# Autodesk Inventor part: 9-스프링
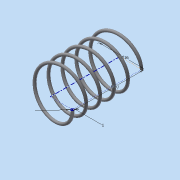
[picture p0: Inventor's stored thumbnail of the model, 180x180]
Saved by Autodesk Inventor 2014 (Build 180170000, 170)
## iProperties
Created: 2015-06
Part Number: 9-스프링
Material: 강철, 연강
Document SubType Name: Modeling
Designer: MYHOME
Density: 7.86 g/cm^3
Appearance: 강철
Mass: 1.52988 g
Surface Area: 7.87024 cm^2
Volume: 0.194641 cm^3
Author: MYHOME
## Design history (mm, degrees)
sketch "스케치1"
  geometry: L1 (0, 0)-(8, 0); L2 (8, 0)-(8, 14.5); L3 (8, 14.5)-(0, 14.5); L4 (0, 14.5)-(0, 0); C1 r 0.5 at (8, 0)
  constraints: 8 end point, 2 parallel, 1 centre point, 1 coincident, 1 horizontal, 1 perpendicular
  dimensions: "d0" = 1 diameter of C1; "d1" = 16 diameter of L2 L4; "d2" = 14.5 distance of L1.end L2.end (derived)
feature "코일1" sketch "스케치1" pitch "d3" = 10; turns "d5" = 5; dims "d4" = 14.5 (= d2), "d6" = 0, angle "d7" = 90 deg, angle "d8" = 90 deg, "d9" = 0, "d10" = 0
sketch "스케치2"
  geometry: L1 (-8.5, 0)-(-7.5, 0) reference; 1 further point
  constraints: 1 horizontal alignment
extrude "돌출1" cut sketch "스케치2" stored distance "d11" = 10; taper "d12" = 0 deg
node "작업 평면1"
sketch "스케치3"
  geometry: L1 (-7.5, 0)-(-8.5, 0) reference; 1 further point
  constraints: 1 horizontal alignment
extrude "돌출2" cut sketch "스케치3" stored distance "d14" = 10; taper "d15" = 0 deg
node "솔리드1"
node "절단 모서리 투영1"
node "절단 모서리 투영2"
other parameters: "d13" = 14.5 (= d2)
